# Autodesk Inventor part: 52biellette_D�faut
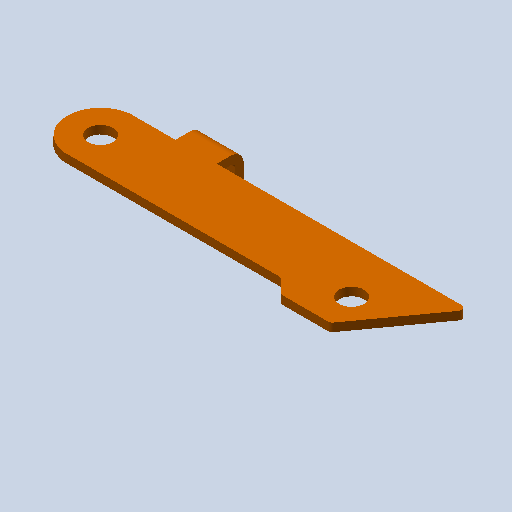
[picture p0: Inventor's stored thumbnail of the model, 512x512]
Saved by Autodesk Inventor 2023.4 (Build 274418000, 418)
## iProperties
Created: 2011-01
Part Number: 52biellette_D�faut
Document SubType Name: Modeling
Designer: eric
Density: 1 g/cm^3
Mass: 2.95797 g
Surface Area: 35.1572 cm^2
Volume: 2.95797 cm^3
Material: Générique
Appearance: 255,128,0_1
Author: eric
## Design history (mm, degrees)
feature "Base1"
node "Corps solides"
node "Corps surfaciques"
node "Solide1"
